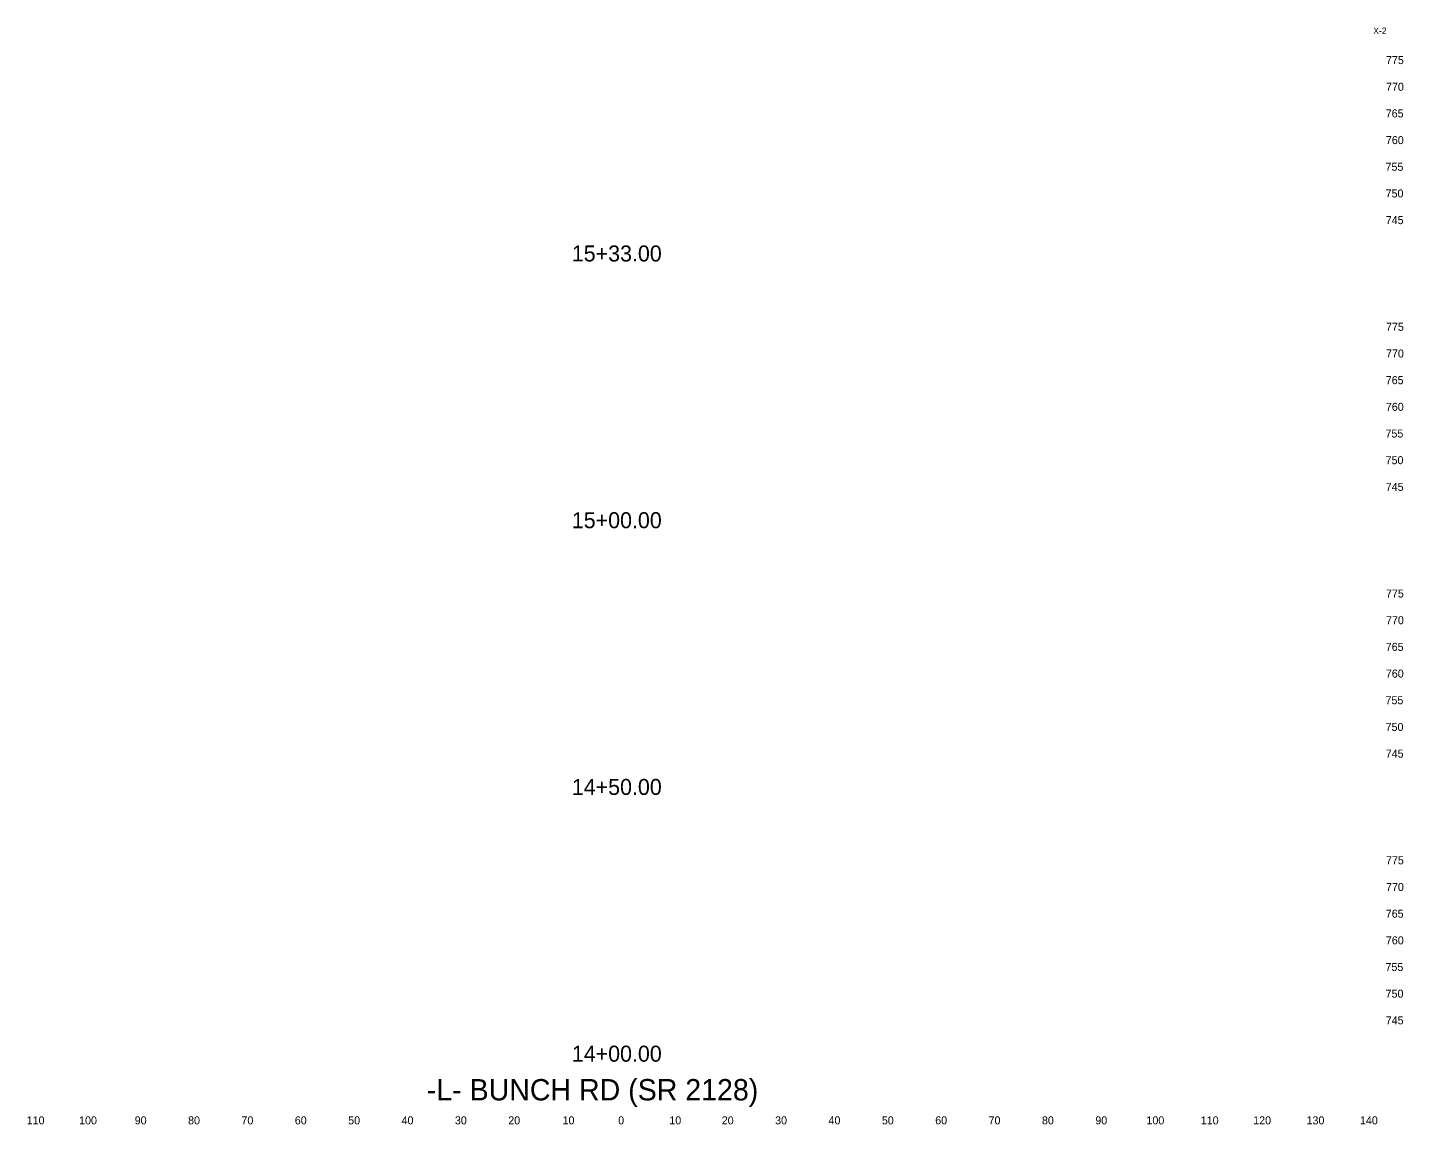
# Model space of a CAD drawing. Extents: x 2473106 to 2475402, y 633617 to 633851.
# Drawn here: x 2473944.5 to 2474202.3, y 633618.8 to 633824.4 of the extents above; entities that cross this region are included whole.
import ezdxf

# ---------------------------------------------------------------- set-up
doc = ezdxf.new("R2010")
doc.units = 0
for name, color, linetype in [('Exist Cross Section Cell', 7, 'Continuous'), ('Exist XS Center Line Elevation Label', 7, 'Continuous'), ('Exist XS Ground Line', 7, 'Continuous'), ('Prop XS SE Text', 7, 'Continuous'), ('Scratch_Level_5', 7, 'Continuous')]:
    doc.layers.add(name, color=color, linetype=linetype)

msp = doc.modelspace()

# ---------------------------------------------------------------- texts
at = {"layer": 'Exist Cross Section Cell'}
for s, p in [('110', (2473944.31, 633618.82)), ('100', (2473954.13, 633618.82)), ('90', (2473964.55, 633618.82)), ('80', (2473974.55, 633618.82)), ('70', (2473984.55, 633618.82)), ('60', (2473994.55, 633618.82)), ('50', (2474004.55, 633618.82)), ('40', (2474014.55, 633618.82)), ('30', (2474024.55, 633618.82)), ('20', (2474034.55, 633618.82)), ('10', (2474044.73, 633618.82)), ('0', (2474055.14, 633618.82)), ('0', (2474055.14, 633618.82)), ('10', (2474064.73, 633618.82)), ('20', (2474074.55, 633618.82)), ('30', (2474084.55, 633618.82)), ('40', (2474094.55, 633618.82)), ('50', (2474104.55, 633618.82)), ('60', (2474114.55, 633618.82)), ('70', (2474124.55, 633618.82)), ('80', (2474134.55, 633618.82)), ('90', (2474144.55, 633618.82)), ('100', (2474154.13, 633618.82)), ('110', (2474164.31, 633618.82)), ('120', (2474174.13, 633618.82)), ('130', (2474184.13, 633618.82)), ('140', (2474194.13, 633618.82))]:
    msp.add_text(s, height=1.5, dxfattribs=at).set_placement(p)
at = {"layer": 'Exist XS Center Line Elevation Label'}
for s, p in [('15+33.00', (2474046.46, 633780.57)), ('15+00.00', (2474046.46, 633730.57)), ('14+50.00', (2474046.46, 633680.57)), ('14+00.00', (2474046.46, 633630.57))]:
    msp.add_text(s, height=3, dxfattribs=at).set_placement(p)
at = {"layer": 'Exist XS Ground Line'}
for s, p in [('775', (2474199.01, 633817.57)), ('770', (2474199.02, 633812.57)), ('765', (2474198.97, 633807.57)), ('760', (2474198.99, 633802.57)), ('755', (2474198.92, 633797.57)), ('750', (2474198.94, 633792.57)), ('745', (2474198.97, 633787.57)), ('775', (2474199.01, 633767.57)), ('770', (2474199.02, 633762.57)), ('765', (2474198.97, 633757.57)), ('760', (2474198.99, 633752.57)), ('755', (2474198.92, 633747.57)), ('750', (2474198.94, 633742.57)), ('745', (2474198.97, 633737.57)), ('775', (2474199.01, 633717.57)), ('770', (2474199.02, 633712.57)), ('765', (2474198.97, 633707.57)), ('760', (2474198.99, 633702.57)), ('755', (2474198.92, 633697.57)), ('750', (2474198.94, 633692.57)), ('745', (2474198.97, 633687.57)), ('775', (2474199.01, 633667.57)), ('770', (2474199.02, 633662.57)), ('765', (2474198.97, 633657.57)), ('760', (2474198.99, 633652.57)), ('755', (2474198.92, 633647.57)), ('750', (2474198.94, 633642.57)), ('745', (2474198.97, 633637.57))]:
    msp.add_text(s, height=1.5, dxfattribs=at).set_placement(p)
at = {"layer": 'Prop XS SE Text'}
msp.add_text('X-2', height=1.2, dxfattribs=at).set_placement((2474196.62, 633823.21))
at = {"layer": 'Scratch_Level_5'}
msp.add_text('-L- BUNCH RD (SR 2128)', height=4, dxfattribs=at).set_placement((2474019.28, 633623.31))

doc.saveas('drawing.dxf')
